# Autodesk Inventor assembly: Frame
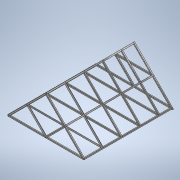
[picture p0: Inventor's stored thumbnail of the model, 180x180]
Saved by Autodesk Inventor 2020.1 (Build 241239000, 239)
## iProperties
_SolveAssemblyDoc: Frame Generator Solve Assembly
_Version: 15.0.0
Created: 2019-10
Part Number: Frame
Document SubType Name: Weldment
Designer: Synergysoft Dell02
Weld Material: Welded Aluminum-6061
Author: Synergysoft Dell02
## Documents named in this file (4)
- C:\Users\Synergysoft Dell02\Desktop\INV-01 Intro to Modeling_2020\FRAME\Frame.iam
- C:\Users\Synergysoft Dell02\Desktop\INV-01 Intro to Modeling_2020\FRAME\Frame.ipt
- C:\Users\Synergysoft Dell02\Desktop\INV-01 Intro to Modeling_2020\FRAME\Frame\Frame\Frame 1572343187933.iam
- C:\Users\Synergysoft Dell02\Desktop\INV-01 Intro to Modeling_2020\FRAME\Frame_Substitute_1.ipt
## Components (3 placed, 3 different names)
1. Frame:1
2. Frame 1572343187933:1 [sub-assembly]
3. Frame_Substitute_1:1
